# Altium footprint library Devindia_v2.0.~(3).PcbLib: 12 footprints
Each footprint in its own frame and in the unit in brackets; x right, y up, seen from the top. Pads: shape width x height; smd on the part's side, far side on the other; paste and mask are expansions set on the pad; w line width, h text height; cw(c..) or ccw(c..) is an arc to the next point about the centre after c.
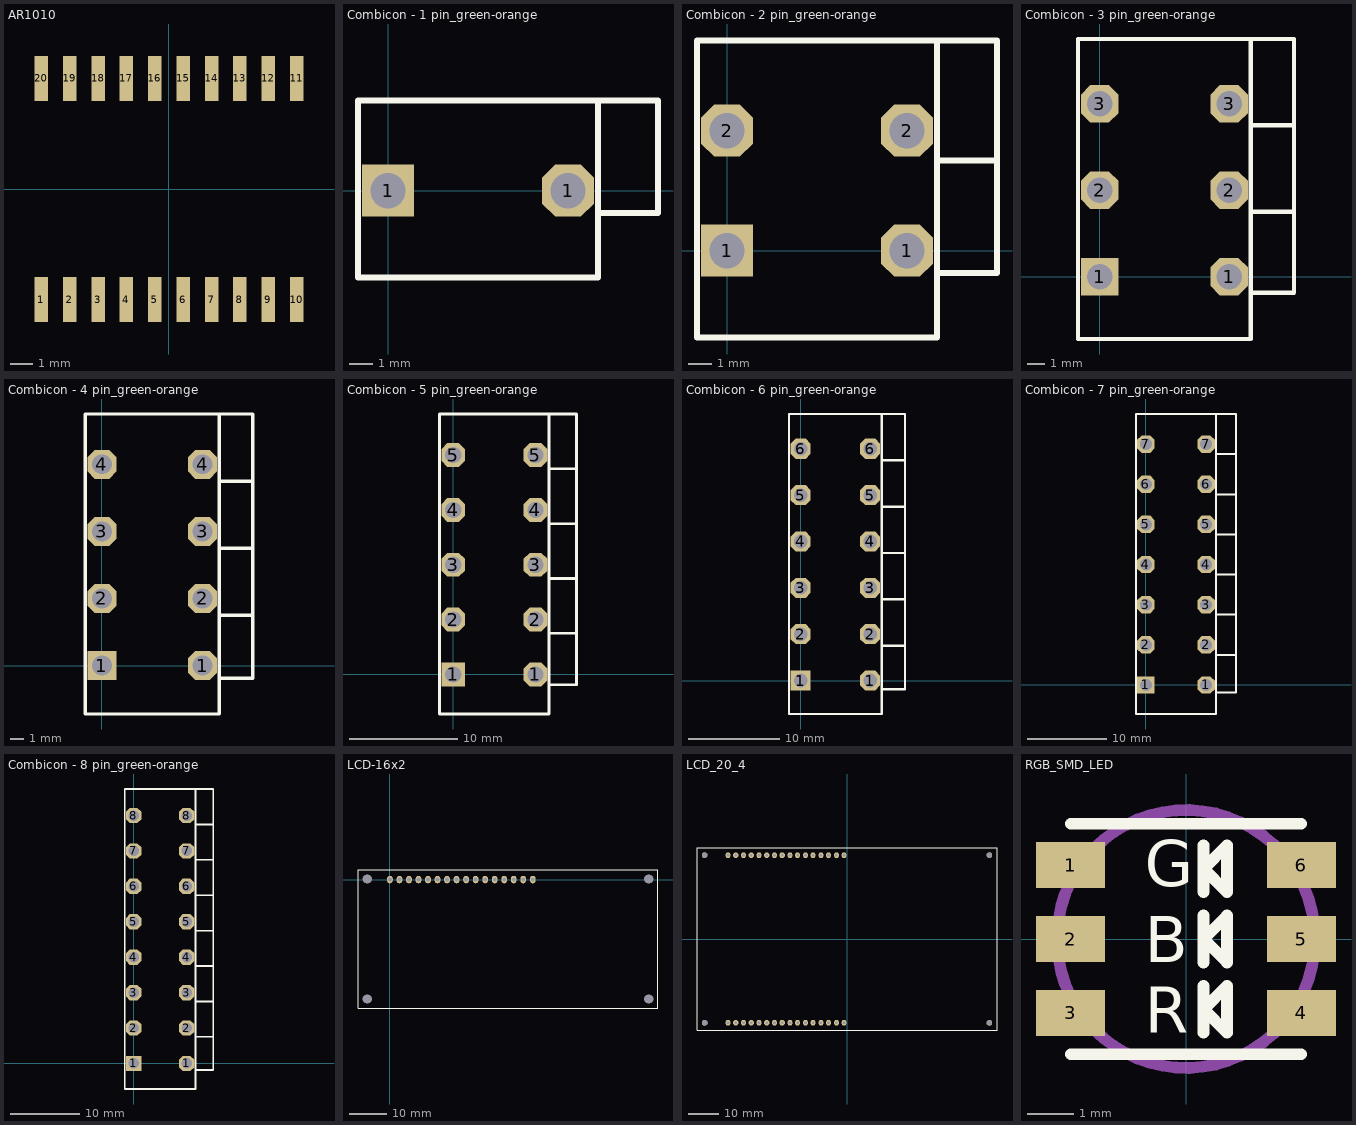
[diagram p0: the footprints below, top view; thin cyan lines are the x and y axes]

## AR1010 [mm]
pads (20):
  rect 0.6x2 smd: 1(-5.715,-4.95) 2(-4.445,-4.95) 3(-3.175,-4.95) 4(-1.905,-4.95) 5(-0.635,-4.95) 6(0.635,-4.95) 7(1.905,-4.95) 8(3.175,-4.95) 9(4.445,-4.95) 10(5.715,-4.95) 11(5.715,4.95) 12(4.445,4.95) 13(3.175,4.95) 14(1.905,4.95) 15(0.635,4.95) 16(-0.635,4.95) 17(-1.905,4.95) 18(-3.175,4.95) 19(-4.445,4.95) 20(-5.715,4.95)
Bottom Overlay:
  circle w0.254: c-5.695,-3.115 r0.284
  lines w0.254: -6.4,-3.75 -6.4,3.75 6.4,3.75 6.4,-3.75 -6.4,-3.75
3D body: height 2.15, standoff 2.05, extent -5.969,-2.54 -5.46,-2.034
3D body: height 0.32, standoff 0, extent -5.969,-5.588 -5.461,-4.318
3D body: height 1, standoff 0.16, extent -5.969,-4.445 -5.461,-4.191
3D body: height 0.32, standoff 0, extent -5.969,-4.51 -5.461,-4.191
3D body: height 1.16, standoff 0.84, extent -5.969,-4.445 -5.461,-4.126
3D body: height 1.16, standoff 0.84, extent -5.969,-4.318 -5.461,-3.175
3D body: height 0.32, standoff 0, extent -4.699,-5.588 -4.191,-4.318
3D body: height 1, standoff 0.16, extent -4.699,-4.445 -4.191,-4.191
3D body: height 0.32, standoff 0, extent -4.699,-4.51 -4.191,-4.191
3D body: height 1.16, standoff 0.84, extent -4.699,-4.445 -4.191,-4.126
3D body: height 1.16, standoff 0.84, extent -4.699,-4.318 -4.191,-3.175
3D body: height 0.32, standoff 0, extent -3.429,-5.588 -2.921,-4.318
3D body: height 1, standoff 0.16, extent -3.429,-4.445 -2.921,-4.191
3D body: height 0.32, standoff 0, extent -3.429,-4.51 -2.921,-4.191
3D body: height 1.16, standoff 0.84, extent -3.429,-4.445 -2.921,-4.126
3D body: height 1.16, standoff 0.84, extent -3.429,-4.318 -2.921,-3.175
3D body: height 0.32, standoff 0, extent -2.159,-5.588 -1.651,-4.318
3D body: height 1, standoff 0.16, extent -2.159,-4.445 -1.651,-4.191
3D body: height 0.32, standoff 0, extent -2.159,-4.51 -1.651,-4.191
3D body: height 1.16, standoff 0.84, extent -2.159,-4.445 -1.651,-4.126
3D body: height 1.16, standoff 0.84, extent -2.159,-4.318 -1.651,-3.175
3D body: height 0.32, standoff 0, extent -0.889,-5.588 -0.381,-4.318
3D body: height 1, standoff 0.16, extent -0.889,-4.445 -0.381,-4.191
3D body: height 0.32, standoff 0, extent -0.889,-4.51 -0.381,-4.191
3D body: height 1.16, standoff 0.84, extent -0.889,-4.445 -0.381,-4.126
3D body: height 1.16, standoff 0.84, extent -0.889,-4.318 -0.381,-3.175
3D body: height 0.32, standoff 0, extent 0.381,-5.588 0.889,-4.318
3D body: height 1, standoff 0.16, extent 0.381,-4.445 0.889,-4.191
3D body: height 0.32, standoff 0, extent 0.381,-4.51 0.889,-4.191
3D body: height 1.16, standoff 0.84, extent 0.381,-4.445 0.889,-4.126
3D body: height 1.16, standoff 0.84, extent 0.381,-4.318 0.889,-3.175
3D body: height 0.32, standoff 0, extent 1.651,-5.588 2.159,-4.318
3D body: height 1, standoff 0.16, extent 1.651,-4.445 2.159,-4.191
3D body: height 0.32, standoff 0, extent 1.651,-4.51 2.159,-4.191
3D body: height 1.16, standoff 0.84, extent 1.651,-4.445 2.159,-4.126
3D body: height 1.16, standoff 0.84, extent 1.651,-4.318 2.159,-3.175
3D body: height 0.32, standoff 0, extent 2.921,-5.588 3.429,-4.318
3D body: height 1, standoff 0.16, extent 2.921,-4.445 3.429,-4.191
3D body: height 0.32, standoff 0, extent 2.921,-4.51 3.429,-4.191
3D body: height 1.16, standoff 0.84, extent 2.921,-4.445 3.429,-4.126
3D body: height 1.16, standoff 0.84, extent 2.921,-4.318 3.429,-3.175
3D body: height 0.32, standoff 0, extent 4.191,-5.588 4.699,-4.318
3D body: height 1, standoff 0.16, extent 4.191,-4.445 4.699,-4.191
3D body: height 0.32, standoff 0, extent 4.191,-4.51 4.699,-4.191
3D body: height 1.16, standoff 0.84, extent 4.191,-4.445 4.699,-4.126
3D body: height 1.16, standoff 0.84, extent 4.191,-4.318 4.699,-3.175
3D body: height 0.32, standoff 0, extent 5.461,-5.588 5.969,-4.318
3D body: height 1, standoff 0.16, extent 5.461,-4.445 5.969,-4.191
3D body: height 0.32, standoff 0, extent 5.461,-4.51 5.969,-4.191
3D body: height 1.16, standoff 0.84, extent 5.461,-4.445 5.969,-4.126
3D body: height 1.16, standoff 0.84, extent 5.461,-4.318 5.969,-3.175
3D body: height 0.32, standoff 0, extent 5.461,4.318 5.969,5.588
3D body: height 1, standoff 0.16, extent 5.461,4.191 5.969,4.445
3D body: height 0.32, standoff 0, extent 5.461,4.191 5.969,4.51
3D body: height 1.16, standoff 0.84, extent 5.461,4.126 5.969,4.445
3D body: height 1.16, standoff 0.84, extent 5.461,3.175 5.969,4.318
3D body: height 0.32, standoff 0, extent 4.191,4.318 4.699,5.588
3D body: height 1, standoff 0.16, extent 4.191,4.191 4.699,4.445
3D body: height 0.32, standoff 0, extent 4.191,4.191 4.699,4.51
3D body: height 1.16, standoff 0.84, extent 4.191,4.126 4.699,4.445
3D body: height 1.16, standoff 0.84, extent 4.191,3.175 4.699,4.318
3D body: height 0.32, standoff 0, extent 2.921,4.318 3.429,5.588
3D body: height 1, standoff 0.16, extent 2.921,4.191 3.429,4.445
3D body: height 0.32, standoff 0, extent 2.921,4.191 3.429,4.51
3D body: height 1.16, standoff 0.84, extent 2.921,4.126 3.429,4.445
3D body: height 1.16, standoff 0.84, extent 2.921,3.175 3.429,4.318
3D body: height 0.32, standoff 0, extent 1.651,4.318 2.159,5.588
3D body: height 1, standoff 0.16, extent 1.651,4.191 2.159,4.445
3D body: height 0.32, standoff 0, extent 1.651,4.191 2.159,4.51
3D body: height 1.16, standoff 0.84, extent 1.651,4.126 2.159,4.445
3D body: height 1.16, standoff 0.84, extent 1.651,3.175 2.159,4.318
3D body: height 0.32, standoff 0, extent 0.381,4.318 0.889,5.588
3D body: height 1, standoff 0.16, extent 0.381,4.191 0.889,4.445
3D body: height 0.32, standoff 0, extent 0.381,4.191 0.889,4.51
3D body: height 1.16, standoff 0.84, extent 0.381,4.126 0.889,4.445
3D body: height 1.16, standoff 0.84, extent 0.381,3.175 0.889,4.318
3D body: height 0.32, standoff 0, extent -0.889,4.318 -0.381,5.588
3D body: height 1, standoff 0.16, extent -0.889,4.191 -0.381,4.445
3D body: height 0.32, standoff 0, extent -0.889,4.191 -0.381,4.51
3D body: height 1.16, standoff 0.84, extent -0.889,4.126 -0.381,4.445
3D body: height 1.16, standoff 0.84, extent -0.889,3.175 -0.381,4.318
3D body: height 0.32, standoff 0, extent -2.159,4.318 -1.651,5.588
3D body: height 1, standoff 0.16, extent -2.159,4.191 -1.651,4.445
3D body: height 0.32, standoff 0, extent -2.159,4.191 -1.651,4.51
3D body: height 1.16, standoff 0.84, extent -2.159,4.126 -1.651,4.445
3D body: height 1.16, standoff 0.84, extent -2.159,3.175 -1.651,4.318
3D body: height 0.32, standoff 0, extent -3.429,4.318 -2.921,5.588
3D body: height 1, standoff 0.16, extent -3.429,4.191 -2.921,4.445
3D body: height 0.32, standoff 0, extent -3.429,4.191 -2.921,4.51
3D body: height 1.16, standoff 0.84, extent -3.429,4.126 -2.921,4.445
3D body: height 1.16, standoff 0.84, extent -3.429,3.175 -2.921,4.318
3D body: height 0.32, standoff 0, extent -4.699,4.318 -4.191,5.588
3D body: height 1, standoff 0.16, extent -4.699,4.191 -4.191,4.445
3D body: height 1.16, standoff 0.84, extent -4.699,3.175 -4.191,4.318
3D body: height 0.32, standoff 0, extent -4.699,4.191 -4.191,4.51
3D body: height 1.16, standoff 0.84, extent -4.699,4.126 -4.191,4.445
3D body: height 0.32, standoff 0, extent -5.969,4.318 -5.461,5.588
3D body: height 1, standoff 0.16, extent -5.969,4.191 -5.461,4.445
3D body: height 1.16, standoff 0.84, extent -5.969,3.175 -5.461,4.318
3D body: height 0.32, standoff 0, extent -5.969,4.191 -5.461,4.51
3D body: height 1.16, standoff 0.84, extent -5.969,4.126 -5.461,4.445
3D body: height 1.18, standoff 0.1, extent -6.35,-3.81 6.35,3.81
3D body: height 2.05, standoff 1.05, extent -6.35,-3.175 6.35,3.175

## Combicon - 1 pin_green-orange [mm]
pads (2):
  rect 2.2x2.2 hole 1.5: 1(0,0)
  oct 2.2x2.2 hole 1.5: 1(7.62,0)
Top Overlay:
  lines w0.254: 8.956,-0.95 11.43,-0.95 11.43,3.81 8.89,3.81 ; 8.89,3.81 -1.27,3.81 -1.27,0.07 -1.27,-3.67 8.89,-3.67 8.89,3.81
3D body: height 13.66, standoff 7.75, extent 8.89,-1.016 11.43,3.81
3D body: height 13.5, standoff 13, extent 5.969,-1.503 8.864,1.397
3D body: height 13, standoff 0, extent -1.27,-3.683 8.89,3.81

## Combicon - 2 pin_green-orange [mm]
pads (4):
  rect 2.2x2.2 hole 1.5: 1(0,0)
  oct 2.2x2.2 hole 1.5: 1(7.62,0) 2(0,5.08) 2(7.62,5.08)
Top Overlay:
  lines w0.254: 8.956,-0.95 11.43,-0.95 11.43,3.81 ; 8.89,3.81 8.89,8.89 ; 8.89,3.81 8.89,-3.67 -1.27,-3.67 -1.27,0.07 -1.27,8.89 8.89,8.89 ; 8.89,3.81 11.43,3.81 ; 8.89,8.89 11.43,8.89 11.43,3.81
3D body: height 13, standoff 0, extent -1.27,-3.683 8.89,8.89
3D body: height 13.5, standoff 13, extent 5.969,-1.503 8.864,1.397
3D body: height 13.5, standoff 13, extent 5.969,3.577 8.864,6.477
3D body: height 13.66, standoff 7.75, extent 8.89,4.064 11.43,8.89
3D body: height 13.66, standoff 7.75, extent 8.89,-1.016 11.43,3.81

## Combicon - 3 pin_green-orange [mm]
pads (6):
  rect 2.2x2.2 hole 1.5: 1(0,0)
  oct 2.2x2.2 hole 1.5: 1(7.62,0) 2(0,5.08) 2(7.62,5.08) 3(0,10.16) 3(7.62,10.16)
Top Overlay:
  lines w0.254: 8.89,8.89 11.43,8.89 ; 8.956,-0.95 11.43,-0.95 11.43,3.81 ; 8.89,3.81 8.89,13.97 ; 8.89,3.81 8.89,-3.67 -1.27,-3.67 -1.27,0.07 -1.27,13.97 8.89,13.97 ; 8.89,3.81 11.43,3.81 ; 8.89,13.97 11.43,13.97 11.43,8.89 ; 11.43,3.81 11.43,8.89
3D body: height 13, standoff 0, extent -1.27,-3.683 8.89,13.97
3D body: height 13.5, standoff 13, extent 5.969,-1.503 8.864,1.397
3D body: height 13.5, standoff 13, extent 5.969,3.577 8.864,6.477
3D body: height 13.5, standoff 13, extent 5.969,8.657 8.864,11.557
3D body: height 13.66, standoff 7.75, extent 8.89,9.144 11.43,13.97
3D body: height 13.66, standoff 7.75, extent 8.89,4.064 11.43,8.89
3D body: height 13.66, standoff 7.75, extent 8.89,-1.016 11.43,3.81

## Combicon - 4 pin_green-orange [mm]
pads (8):
  rect 2.2x2.2 hole 1.5: 1(0,0)
  oct 2.2x2.2 hole 1.5: 1(7.62,0) 2(0,5.08) 2(7.62,5.08) 3(0,10.16) 3(7.62,10.16) 4(0,15.24) 4(7.62,15.24)
Top Overlay:
  lines w0.254: 8.89,8.89 11.43,8.89 ; 8.89,13.97 11.43,13.97 ; 8.956,-0.95 11.43,-0.95 11.43,3.81 ; 8.89,3.81 8.89,19.05 ; 8.89,3.81 8.89,-3.67 -1.27,-3.67 -1.27,0.07 -1.27,19.05 8.89,19.05 ; 8.89,3.81 11.43,3.81 ; 8.89,19.05 11.43,19.05 11.43,13.97 ; 11.43,3.81 11.43,8.89 ; 11.43,8.89 11.43,13.97
3D body: height 13, standoff 0, extent -1.27,-3.683 8.89,19.05
3D body: height 13.5, standoff 13, extent 5.969,-1.503 8.864,1.397
3D body: height 13.5, standoff 13, extent 5.969,3.577 8.864,6.477
3D body: height 13.5, standoff 13, extent 5.969,8.657 8.864,11.557
3D body: height 13.5, standoff 13, extent 5.969,13.737 8.864,16.637
3D body: height 13.66, standoff 7.75, extent 8.89,14.224 11.43,19.05
3D body: height 13.66, standoff 7.75, extent 8.89,9.144 11.43,13.97
3D body: height 13.66, standoff 7.75, extent 8.89,4.064 11.43,8.89
3D body: height 13.66, standoff 7.75, extent 8.89,-1.016 11.43,3.81

## Combicon - 5 pin_green-orange [mm]
pads (10):
  rect 2.2x2.2 hole 1.5: 1(0,0)
  oct 2.2x2.2 hole 1.5: 1(7.62,0) 2(0,5.08) 2(7.62,5.08) 3(0,10.16) 3(7.62,10.16) 4(0,15.24) 4(7.62,15.24) 5(0,20.32) 5(7.62,20.32)
Top Overlay:
  lines w0.254: 8.89,8.89 11.43,8.89 ; 8.89,13.97 11.43,13.97 ; 8.89,19.05 11.43,19.05 ; 8.956,-0.95 11.43,-0.95 11.43,3.81 ; 8.89,3.81 11.43,3.81 ; 8.89,3.81 8.89,-3.67 -1.27,-3.67 -1.27,0.07 -1.27,24.13 8.89,24.13 ; 8.89,3.81 8.89,24.13 ; 8.89,24.13 11.43,24.13 11.43,19.05 ; 11.43,3.81 11.43,8.89 ; 11.43,8.89 11.43,13.97 ; 11.43,13.97 11.43,19.05
3D body: height 13.66, standoff 7.75, extent 8.89,-1.016 11.43,3.81
3D body: height 13.66, standoff 7.75, extent 8.89,4.064 11.43,8.89
3D body: height 13.66, standoff 7.75, extent 8.89,9.144 11.43,13.97
3D body: height 13.66, standoff 7.75, extent 8.89,14.224 11.43,19.05
3D body: height 13.66, standoff 7.75, extent 8.89,19.304 11.43,24.13
3D body: height 13.5, standoff 13, extent 5.969,18.817 8.864,21.717
3D body: height 13.5, standoff 13, extent 5.969,13.737 8.864,16.637
3D body: height 13.5, standoff 13, extent 5.969,8.657 8.864,11.557
3D body: height 13.5, standoff 13, extent 5.969,3.577 8.864,6.477
3D body: height 13.5, standoff 13, extent 5.969,-1.503 8.864,1.397
3D body: height 13, standoff 0, extent -1.27,-3.683 8.89,24.13

## Combicon - 6 pin_green-orange [mm]
pads (12):
  rect 2.2x2.2 hole 1.5: 1(0,0)
  oct 2.2x2.2 hole 1.5: 1(7.62,0) 2(0,5.08) 2(7.62,5.08) 3(0,10.16) 3(7.62,10.16) 4(0,15.24) 4(7.62,15.24) 5(0,20.32) 5(7.62,20.32) 6(0,25.4) 6(7.62,25.4)
Top Overlay:
  lines w0.254: 8.89,8.89 11.43,8.89 ; 8.89,13.97 11.43,13.97 ; 8.89,19.05 11.43,19.05 ; 8.89,24.13 11.43,24.13 ; 8.956,-0.95 11.43,-0.95 11.43,3.81 ; 8.89,3.81 8.89,29.21 ; 8.89,3.81 8.89,-3.67 -1.27,-3.67 -1.27,0.07 -1.27,29.21 8.89,29.21 ; 8.89,3.81 11.43,3.81 ; 8.89,29.21 11.43,29.21 11.43,24.13 ; 11.43,3.81 11.43,8.89 ; 11.43,8.89 11.43,13.97 ; 11.43,13.97 11.43,19.05 ; 11.43,19.05 11.43,24.13
3D body: height 13, standoff 0, extent -1.27,-3.683 8.89,29.21
3D body: height 13.5, standoff 13, extent 5.969,-1.503 8.864,1.397
3D body: height 13.5, standoff 13, extent 5.969,3.577 8.864,6.477
3D body: height 13.5, standoff 13, extent 5.969,8.657 8.864,11.557
3D body: height 13.5, standoff 13, extent 5.969,13.737 8.864,16.637
3D body: height 13.5, standoff 13, extent 5.969,18.817 8.864,21.717
3D body: height 13.5, standoff 13, extent 5.969,23.897 8.864,26.797
3D body: height 13.66, standoff 7.75, extent 8.89,24.384 11.43,29.21
3D body: height 13.66, standoff 7.75, extent 8.89,19.304 11.43,24.13
3D body: height 13.66, standoff 7.75, extent 8.89,14.224 11.43,19.05
3D body: height 13.66, standoff 7.75, extent 8.89,9.144 11.43,13.97
3D body: height 13.66, standoff 7.75, extent 8.89,4.064 11.43,8.89
3D body: height 13.66, standoff 7.75, extent 8.89,-1.016 11.43,3.81

## Combicon - 7 pin_green-orange [mm]
pads (14):
  rect 2.2x2.2 hole 1.5: 1(0,0)
  oct 2.2x2.2 hole 1.5: 1(7.62,0) 2(0,5.08) 2(7.62,5.08) 3(0,10.16) 3(7.62,10.16) 4(0,15.24) 4(7.62,15.24) 5(0,20.32) 5(7.62,20.32) 6(0,25.4) 6(7.62,25.4) 7(0,30.48) 7(7.62,30.48)
Top Overlay:
  lines w0.254: 8.89,8.89 11.43,8.89 ; 8.89,13.97 11.43,13.97 ; 8.89,19.05 11.43,19.05 ; 8.89,24.13 11.43,24.13 ; 8.89,29.21 11.43,29.21 ; 8.956,-0.95 11.43,-0.95 11.43,3.81 ; 8.89,3.81 8.89,34.29 ; 8.89,3.81 8.89,-3.67 -1.27,-3.67 -1.27,0.07 -1.27,34.29 8.89,34.29 ; 8.89,3.81 11.43,3.81 ; 8.89,34.29 11.43,34.29 ; 8.89,34.29 11.43,34.29 ; 11.43,3.81 11.43,8.89 ; 11.43,8.89 11.43,13.97 ; 11.43,13.97 11.43,19.05 ; 11.43,19.05 11.43,24.13 ; 11.43,24.13 11.43,29.21 ; 11.43,29.21 11.43,34.29
3D body: height 13, standoff 0, extent -1.27,-3.683 8.89,34.29
3D body: height 13.5, standoff 13, extent 5.969,-1.503 8.864,1.397
3D body: height 13.5, standoff 13, extent 5.969,3.577 8.864,6.477
3D body: height 13.5, standoff 13, extent 5.969,8.657 8.864,11.557
3D body: height 13.5, standoff 13, extent 5.969,13.737 8.864,16.637
3D body: height 13.5, standoff 13, extent 5.969,18.817 8.864,21.717
3D body: height 13.5, standoff 13, extent 5.969,23.897 8.864,26.797
3D body: height 13.5, standoff 13, extent 5.969,28.977 8.864,31.877
3D body: height 13.66, standoff 7.75, extent 9.017,29.464 11.557,34.29
3D body: height 13.66, standoff 7.75, extent 8.89,24.384 11.43,29.21
3D body: height 13.66, standoff 7.75, extent 8.89,19.304 11.43,24.13
3D body: height 13.66, standoff 7.75, extent 8.89,14.224 11.43,19.05
3D body: height 13.66, standoff 7.75, extent 8.89,9.144 11.43,13.97
3D body: height 13.66, standoff 7.75, extent 8.89,4.064 11.43,8.89
3D body: height 13.66, standoff 7.75, extent 8.89,-1.016 11.43,3.81

## Combicon - 8 pin_green-orange [mm]
pads (16):
  rect 2.2x2.2 hole 1.5: 1(0,0)
  oct 2.2x2.2 hole 1.5: 1(7.62,0) 2(0,5.08) 2(7.62,5.08) 3(0,10.16) 3(7.62,10.16) 4(0,15.24) 4(7.62,15.24) 5(0,20.32) 5(7.62,20.32) 6(0,25.4) 6(7.62,25.4) 7(0,30.48) 7(7.62,30.48) 8(0,35.56) 8(7.62,35.56)
Top Overlay:
  lines w0.254: 8.89,8.89 11.43,8.89 ; 8.89,13.97 11.43,13.97 ; 8.89,19.05 11.43,19.05 ; 8.89,24.13 11.43,24.13 ; 8.89,29.21 11.43,29.21 ; 8.89,34.29 11.43,34.29 ; 8.956,-0.95 11.43,-0.95 11.43,3.81 ; 8.89,3.81 11.43,3.81 ; 8.89,3.81 8.89,-3.67 -1.27,-3.67 -1.27,0.07 -1.27,39.37 8.89,39.37 ; 8.89,3.81 8.89,39.37 ; 8.89,39.37 11.43,39.37 11.43,34.29 ; 11.43,3.81 11.43,8.89 ; 11.43,8.89 11.43,13.97 ; 11.43,13.97 11.43,19.05 ; 11.43,19.05 11.43,24.13 ; 11.43,24.13 11.43,29.21 ; 11.43,29.21 11.43,34.29
3D body: height 13.66, standoff 7.75, extent 8.89,-1.016 11.43,3.81
3D body: height 13.66, standoff 7.75, extent 8.89,4.064 11.43,8.89
3D body: height 13.66, standoff 7.75, extent 8.89,9.144 11.43,13.97
3D body: height 13.66, standoff 7.75, extent 8.89,14.224 11.43,19.05
3D body: height 13.66, standoff 7.75, extent 8.89,19.304 11.43,24.13
3D body: height 13.66, standoff 7.75, extent 8.89,24.384 11.43,29.21
3D body: height 13.66, standoff 7.75, extent 9.017,29.464 11.557,34.29
3D body: height 13.66, standoff 7.75, extent 8.89,34.544 11.43,39.37
3D body: height 13.5, standoff 13, extent 5.969,34.057 8.864,36.957
3D body: height 13.5, standoff 13, extent 5.969,28.977 8.864,31.877
3D body: height 13.5, standoff 13, extent 5.969,23.897 8.864,26.797
3D body: height 13.5, standoff 13, extent 5.969,18.817 8.864,21.717
3D body: height 13.5, standoff 13, extent 5.969,13.737 8.864,16.637
3D body: height 13.5, standoff 13, extent 5.969,8.657 8.864,11.557
3D body: height 13.5, standoff 13, extent 5.969,3.577 8.864,6.477
3D body: height 13.5, standoff 13, extent 5.969,-1.503 8.864,1.397
3D body: height 13, standoff 0, extent -1.27,-3.683 8.89,39.37

## LCD-16x2 [mm]
pads (20):
  oval 1.524x2 hole 1: 0(0,0) 1(2.54,0) 2(5.08,0) 3(7.62,0) 4(10.16,0) 5(12.7,0) 6(15.24,0) 7(17.78,0) 8(20.32,0) 9(22.86,0) 10(25.4,0) 11(27.94,0) 12(30.48,0) 13(33.02,0) 14(35.56,0) 15(38.1,0)
  round 1.524 hole 2.5: no(-6,-31.85) no(-6,0.15) no(69,-31.85) no(69,0.15)
Top Overlay:
  lines w0.254: -8.509,-34.35 -8.509,2.032 -8.5,2.041 -8.5,2.65 71.5,2.65 71.5,-34.35 -8.5,-34.35 ; 71.5,1.652 71.501,1.651
3D body: height 11, standoff 9.4, extent -8.382,-34.036 71.374,2.667
3D body: height 9.6, standoff 0, extent -0.508,-0.508 0.49,0.488
3D body: height 9.6, standoff 0, extent 2.032,-0.508 3.03,0.488
3D body: height 9.6, standoff 0, extent 4.572,-0.508 5.57,0.488
3D body: height 9.6, standoff 0, extent 7.112,-0.508 8.11,0.488
3D body: height 9.6, standoff 0, extent 9.652,-0.508 10.65,0.488
3D body: height 9.6, standoff 0, extent 12.192,-0.508 13.19,0.488
3D body: height 9.6, standoff 0, extent 14.732,-0.508 15.73,0.488
3D body: height 9.6, standoff 0, extent 17.272,-0.508 18.27,0.488
3D body: height 9.6, standoff 0, extent 19.812,-0.508 20.81,0.488
3D body: height 9.6, standoff 0, extent 22.352,-0.508 23.35,0.488
3D body: height 9.6, standoff 0, extent 24.892,-0.508 25.89,0.488
3D body: height 9.6, standoff 0, extent 27.432,-0.508 28.43,0.488
3D body: height 9.6, standoff 0, extent 29.972,-0.508 30.97,0.488
3D body: height 9.6, standoff 0, extent 32.512,-0.508 33.51,0.488
3D body: height 9.6, standoff 0, extent 35.052,-0.508 36.05,0.488
3D body: height 9.6, standoff 0, extent 37.592,-0.508 38.59,0.488
3D body: height 20.6, standoff 10.6, extent -3.81,-27.94 66.675,-4.445
3D body: height 21.6, standoff 20.6, extent -1.27,-22.86 64.135,-8.89
3D body: height 14.4, standoff 11, extent 66.675,-25.4 71.12,-7.62
3D body: height 11.5, standoff 11, extent 67.725,-1.2 70.719,1.788
3D body: height 11.5, standoff 11, extent 67.425,-33.325 70.419,-30.337
3D body: height 11.5, standoff 11, extent -7.425,-33.275 -4.431,-30.287
3D body: height 11.5, standoff 11, extent -7.45,-1.4 -4.456,1.588

## LCD_20_4 [mm]
pads (36):
  oct 1.8x1.8 hole 1.7: 0(-46.712,27.5) 0(-46.672,-27.5) 0(46.712,-27.5) 0(46.712,27.5)
  oct 1.7x1.7 hole 0.9: 1(-39.052,-27.46) 1(-39.052,27.46) 2(-36.512,-27.46) 2(-36.512,27.46) 3(-33.972,-27.46) 3(-33.972,27.46) 4(-31.432,-27.46) 4(-31.432,27.46) 5(-28.892,-27.46) 5(-28.892,27.46) 6(-26.352,-27.46) 6(-26.352,27.46) 7(-23.812,-27.46) 7(-23.812,27.46) 8(-21.273,-27.46) 8(-21.273,27.46) 9(-18.732,-27.46) 9(-18.732,27.46) 10(-16.192,-27.46) 10(-16.192,27.46) 11(-13.652,-27.46) 11(-13.652,27.46) 12(-11.112,-27.46) 12(-11.112,27.46) 13(-8.572,-27.46) 13(-8.572,27.46) 14(-6.032,-27.46) 14(-6.032,27.46) 15(-3.492,-27.46) 15(-3.492,27.46) 16(-0.953,-27.46) 16(-0.953,27.46)
Top Overlay:
  lines w0.254: -49.212,-30 -49.212,30 49.212,30 49.212,-30 -49.212,-30
3D body: height 12.5, standoff 12, extent -47.752,26.035 -44.764,29.029
3D body: height 12.5, standoff 12, extent 45.085,25.908 48.073,28.902
3D body: height 12.5, standoff 12, extent 45.339,-28.702 48.327,-25.708
3D body: height 12.5, standoff 12, extent -48.006,-28.956 -45.018,-25.962
3D body: height 21, standoff 20.5, extent -36.195,-11.43 36.83,11.43
3D body: height 20.5, standoff 12, extent -46.99,-19.177 47.117,19.685
3D body: height 12, standoff 10.5, extent -49.276,-30.226 49.911,29.972
3D body: height 12, standoff 10.5
3D body: height 10.8, standoff 0, extent -1.397,-27.94 -0.401,-26.942
3D body: height 10.8, standoff 0, extent -3.937,-27.94 -2.941,-26.942
3D body: height 10.8, standoff 0, extent -6.477,-27.94 -5.481,-26.942
3D body: height 10.8, standoff 0, extent -9.017,-27.94 -8.021,-26.942
3D body: height 10.8, standoff 0, extent -11.557,-27.94 -10.561,-26.942
3D body: height 10.8, standoff 0, extent -14.097,-27.94 -13.101,-26.942
3D body: height 10.8, standoff 0, extent -16.637,-27.94 -15.641,-26.942
3D body: height 10.8, standoff 0, extent -19.177,-27.94 -18.181,-26.942
3D body: height 10.8, standoff 0, extent -21.717,-27.94 -20.721,-26.942
3D body: height 10.8, standoff 0, extent -24.257,-27.94 -23.261,-26.942
3D body: height 10.8, standoff 0, extent -26.924,-27.94 -25.928,-26.942
3D body: height 10.8, standoff 0, extent -29.337,-27.94 -28.341,-26.942
3D body: height 10.8, standoff 0, extent -31.877,-27.94 -30.881,-26.942
3D body: height 10.8, standoff 0, extent -34.417,-27.94 -33.421,-26.942
3D body: height 10.8, standoff 0, extent -36.957,-27.94 -35.961,-26.942
3D body: height 10.8, standoff 0, extent -39.497,-27.94 -38.501,-26.942
3D body: height 10.8, standoff 0, extent -1.397,27.051 -0.401,28.049
3D body: height 10.8, standoff 0, extent -3.937,27.051 -2.941,28.049
3D body: height 10.8, standoff 0, extent -6.477,27.051 -5.481,28.049
3D body: height 10.8, standoff 0, extent -9.017,26.924 -8.021,27.922
3D body: height 10.8, standoff 0, extent -11.557,27.051 -10.561,28.049
3D body: height 10.8, standoff 0, extent -14.097,27.051 -13.101,28.049
3D body: height 10.8, standoff 0, extent -16.637,27.051 -15.641,28.049
3D body: height 10.8, standoff 0, extent -19.177,26.924 -18.181,27.922
3D body: height 10.8, standoff 0, extent -21.717,27.051 -20.721,28.049
3D body: height 10.8, standoff 0, extent -24.257,27.051 -23.261,28.049
3D body: height 10.8, standoff 0, extent -26.924,26.924 -25.928,27.922
3D body: height 10.8, standoff 0, extent -29.337,27.051 -28.341,28.049
3D body: height 10.8, standoff 0, extent -32.004,27.051 -31.008,28.049
3D body: height 10.8, standoff 0, extent -34.544,26.924 -33.548,27.922
3D body: height 10.8, standoff 0, extent -36.957,27.051 -35.961,28.049
3D body: height 10.8, standoff 0, extent -39.624,26.924 -38.628,27.922

## RGB_SMD_LED [mm]
pads (6):
  rect 1.5x1 all layers, no hole: 1(-2.5,1.6) 2(-2.5,0) 3(-2.5,-1.6) 4(2.5,-1.6) 5(2.5,0) 6(2.5,1.6)
Top Overlay:
  lines w0.254: -2.5,-2.5 2.5,-2.5 ; -2.5,2.5 2.5,2.5 ; 0.381,-2.032 0.381,-1.016 0.381,-1.524 ; 0.381,-0.508 0.381,0.508 0.381,0 ; 0.381,1.016 0.381,2.032 0.381,1.524 ; 0.381,-1.524 0.889,-2.032 0.889,-1.016 0.381,-1.524 ; 0.381,0 0.889,-0.508 0.889,0.508 0.381,0 ; 0.381,1.524 0.889,1.016 0.889,2.032 0.381,1.524
  text "R" at -0.889,-2.032 h1
  text "B" at -0.889,-0.508 h1
  text "G" at -0.889,1.143 h1
Mechanical 1:
  circle w0.254: c0,0 r2.794
3D body: height 1.7, standoff 1.68, extent -2.286,-2.794 -0.254,-1.27
3D body: height 1.7, standoff 1.68, extent -0.889,-0.889 2.667,0.889
3D body: height 1.7, standoff 1.68, extent -2.794,-0.381 -1.524,0.381
3D body: height 0.2, standoff 0, extent 1.825,1.27 3.095,1.905
3D body: height 0.2, standoff 0, extent 1.825,-0.33 3.095,0.305
3D body: height 0.2, standoff 0, extent 1.825,-1.93 3.095,-1.295
3D body: height 0.2, standoff 0, extent -3.175,-1.93 -1.905,-1.295
3D body: height 0.2, standoff 0, extent -3.175,-0.33 -1.905,0.305
3D body: height 0.2, standoff 0, extent -3.175,1.27 -1.905,1.905
3D body: height 1.68, standoff 0.2, extent -3.429,-3.175 3.429,3.175
3D body: height 1.7, standoff 1.68, extent -2.286,1.27 -0.254,2.794
3D body: height 1.7, standoff 1.68, extent 0.254,0.762 2.159,2.794
3D body: height 1.7, standoff 1.68, extent 0.381,-2.794 2.159,-0.762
